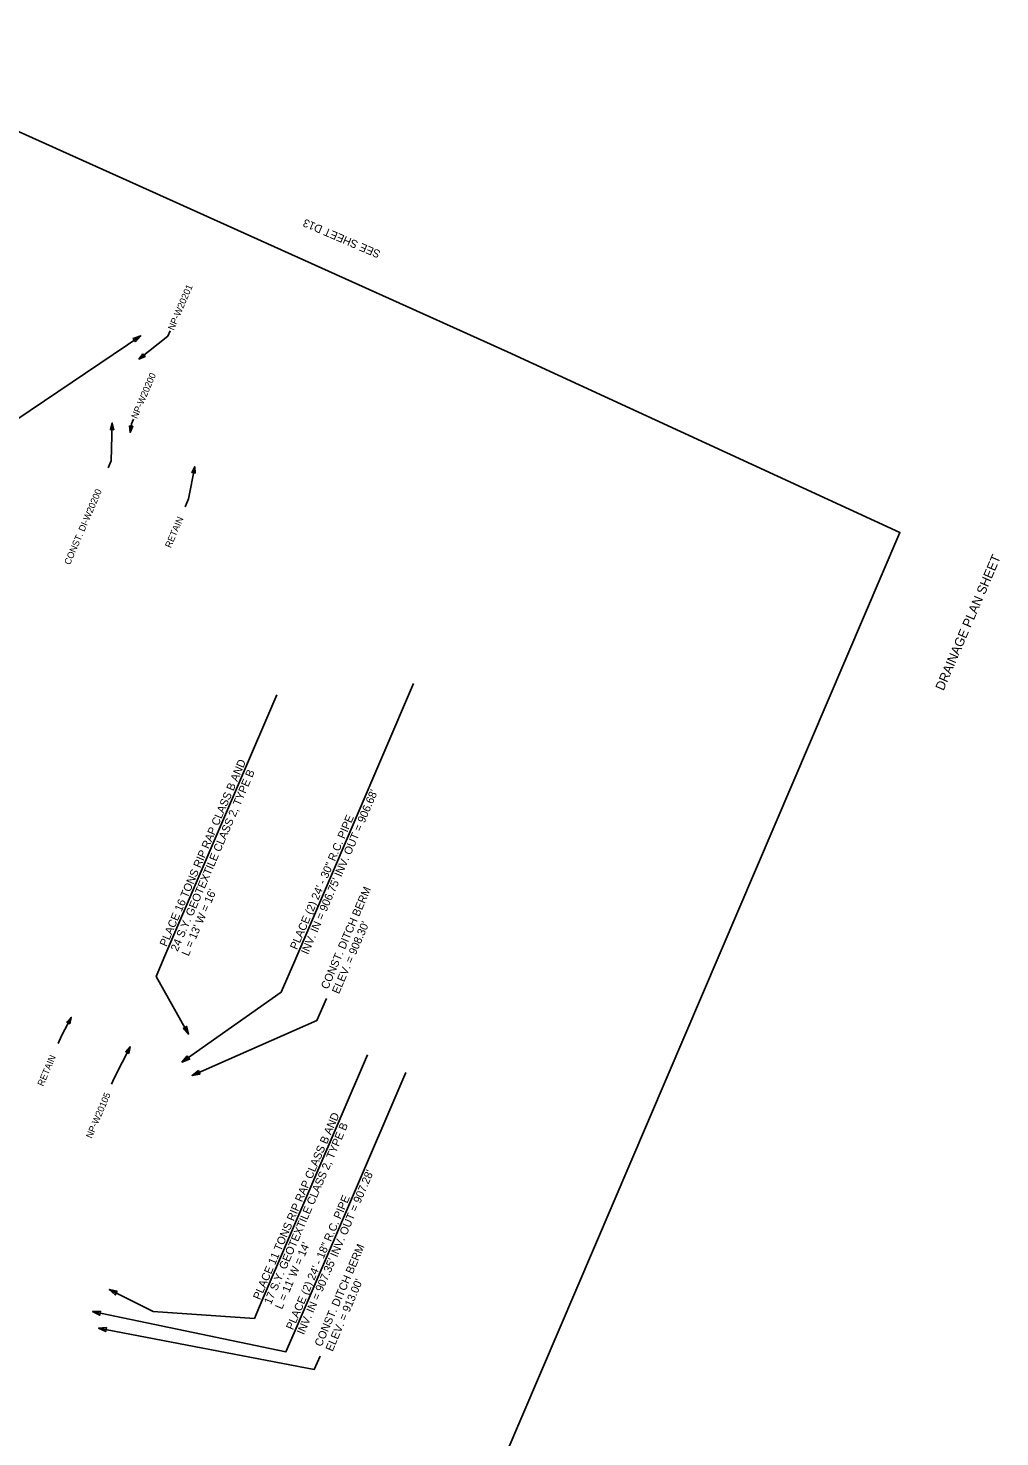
# Model space of a CAD drawing. Extents: x 1615213 to 1616738, y 1098243 to 1100099.
# Drawn here: x 1616009 to 1616738, y 1098952 to 1100008 of the extents above; entities that cross this region are included whole.
import ezdxf

# ---------------------------------------------------------------- set-up
doc = ezdxf.new("R2010")
doc.units = 0
for name, color, linetype in [('Plan_Clip', 7, 'Continuous'), ('RD_SHT_MatchLine', 7, 'Continuous'), ('RD_TX_Drainage', 7, 'Continuous'), ('RD_TX_RoadID', 7, 'Continuous')]:
    doc.layers.add(name, color=color, linetype=linetype)

msp = doc.modelspace()

# ---------------------------------------------------------------- linework, layer by layer
at = {"layer": 'Plan_Clip'}
msp.add_lwpolyline([(1615502.7, 1098507.9), (1615778.5, 1098389.7), (1616070.1, 1098243.5), (1616662.9, 1099630.3), (1616368.7, 1099765.8), (1616095.1, 1099888.9), (1615829.5, 1100008.4), (1615766.4, 1099858.4), (1615733.7, 1099872.1), (1615213.1, 1098634.6)], close=True, dxfattribs=at)
msp.add_lwpolyline([(1615502.7, 1098507.9), (1615778.5, 1098389.7), (1616070.1, 1098243.5), (1616662.9, 1099630.3), (1616368.7, 1099765.8), (1616095.1, 1099888.9), (1615829.5, 1100008.4), (1615766.4, 1099858.4), (1615733.7, 1099872.1), (1615213.1, 1098634.6)], close=True, dxfattribs=at)
msp.add_lwpolyline([(1615502.7, 1098507.9), (1615778.5, 1098389.7), (1616070.1, 1098243.5), (1616662.9, 1099630.3), (1616368.7, 1099765.8), (1616095.1, 1099888.9), (1615829.5, 1100008.4), (1615766.4, 1099858.4), (1615733.7, 1099872.1), (1615213.1, 1098634.6)], close=True, dxfattribs=at)
msp.add_lwpolyline([(1615502.7, 1098507.9), (1615778.5, 1098389.7), (1616070.1, 1098243.5), (1616662.9, 1099630.3), (1616368.7, 1099765.8), (1616095.1, 1099888.9), (1615829.5, 1100008.4), (1615766.4, 1099858.4), (1615733.7, 1099872.1), (1615213.1, 1098634.6)], close=True, dxfattribs=at)
msp.add_lwpolyline([(1615502.7, 1098507.9), (1615778.5, 1098389.7), (1616070.1, 1098243.5), (1616662.9, 1099630.3), (1616368.7, 1099765.8), (1616095.1, 1099888.9), (1615829.5, 1100008.4), (1615766.4, 1099858.4), (1615733.7, 1099872.1), (1615213.1, 1098634.6)], close=True, dxfattribs=at)
msp.add_lwpolyline([(1615502.7, 1098507.9), (1615778.5, 1098389.7), (1616070.1, 1098243.5), (1616662.9, 1099630.3), (1616368.7, 1099765.8), (1616095.1, 1099888.9), (1615829.5, 1100008.4), (1615766.4, 1099858.4), (1615733.7, 1099872.1), (1615213.1, 1098634.6)], close=True, dxfattribs=at)
at = {"layer": 'RD_TX_Drainage'}
for p, q in [((1616298.2, 1099516.9), (1616209, 1099308.9)), ((1616195.7, 1099508.5), (1616111.7, 1099312.7)), ((1616263.7, 1099238.6), (1616183.9, 1099052.8)), ((1616292.3, 1099225.3), (1616208.6, 1099030.1))]:
    msp.add_line(p, q, dxfattribs=at)
for points in [[(1615890.6, 1099613.1), (1615907.4, 1099652.1), (1616093.6, 1099777.7)], [(1616115.7, 1099781.4), (1616114, 1099777.5), (1616092.2, 1099760.2)], [(1616088.1, 1099715.2), (1616086.6, 1099711.8), (1616085.6, 1099705.3)], [(1616069.2, 1099678.8), (1616071.5, 1099684), (1616072.2, 1099712.2)], [(1616126.8, 1099649.5), (1616129.3, 1099655.4), (1616134.1, 1099679.5)], [(1616111.7, 1099312.7), (1616105.1, 1099297.3), (1616129.4, 1099254)], [(1616209, 1099308.9), (1616198.9, 1099285.5), (1616124.5, 1099233.1)], [(1616232.8, 1099280.7), (1616225.7, 1099264.2), (1616132.1, 1099223.1)], [(1616031.7, 1099247.1), (1616034.1, 1099252.8), (1616041.5, 1099266.6)], [(1616071.7, 1099216.5), (1616073.6, 1099220.9), (1616085.6, 1099244.5)], [(1616183.9, 1099052.8), (1616178.8, 1099040.8), (1616103, 1099046.1), (1616069.9, 1099062.5)], [(1616208.6, 1099030.1), (1616202.5, 1099015.8), (1616057.5, 1099045.9)], [(1616228, 1099012.6), (1616223.7, 1099002.6), (1616061.9, 1099033.6)]]:
    msp.add_lwpolyline(points, dxfattribs=at)
for points in [[(1616089.7, 1099773.1), (1616093.6, 1099777.7), (1616088, 1099775.7)], [(1616095.2, 1099764.2), (1616092.2, 1099760.2), (1616096.8, 1099762.2)], [(1616073.4, 1099707.3), (1616072.2, 1099712.2), (1616070.8, 1099707.4)], [(1616085.1, 1099710.3), (1616085.6, 1099705.3), (1616087.6, 1099709.9)], [(1616134.5, 1099674.6), (1616134.1, 1099679.5), (1616131.9, 1099675.1)], [(1616040.4, 1099261.8), (1616041.5, 1099266.6), (1616038.1, 1099263)], [(1616125.3, 1099258.3), (1616129.4, 1099254), (1616128, 1099259.8)], [(1616084.6, 1099239.6), (1616085.6, 1099244.5), (1616082.3, 1099240.8)], [(1616128.4, 1099237.7), (1616124.5, 1099233.1), (1616130.2, 1099235.2)], [(1616136.8, 1099226.8), (1616132.1, 1099223.1), (1616138, 1099224)], [(1616075.8, 1099061.3), (1616069.9, 1099062.5), (1616074.4, 1099058.5)], [(1616063.5, 1099046.3), (1616057.5, 1099045.9), (1616062.8, 1099043.2)], [(1616067.9, 1099034.1), (1616061.9, 1099033.6), (1616067.3, 1099031)]]:
    msp.add_lwpolyline(points, close=True, dxfattribs=at)

# ---------------------------------------------------------------- texts
at = {"layer": 'RD_SHT_MatchLine'}
msp.add_text('SEE SHEET D13', height=6, rotation=156.8359, dxfattribs=at).set_placement((1616273.9, 1099841.2))
at = {"layer": 'RD_TX_Drainage'}
for s, height, p in [('NP-W20201', 5, (1616118.3, 1099781.4)), ('NP-W20200', 5, (1616090.8, 1099715.1)), ('CONST. DI-W20200', 5, (1616040.5, 1099605.5)), ('RETAIN', 5, (1616116.1, 1099618.2)), ('PLACE 16 TONS RIP RAP CLASS B AND', 6, (1616112.9, 1099319.2)), ('24 S.Y. GEOTEXTILE CLASS 2, TYPE B', 6, (1616121.2, 1099315.6)), ("INV. IN = 906.75' INV. OUT = 906.68'", 6, (1616219, 1099313.3)), ('PLACE (2) 24\' - 30" R.C. PIPE', 6, (1616210.7, 1099316.9)), ("L = 13' W = 16'", 6, (1616129.4, 1099312.1)), ('CONST. DITCH BERM', 6, (1616233.9, 1099287.2)), ("ELEV. = 908.30'", 6, (1616242.2, 1099283.7)), ('RETAIN', 5, (1616020.4, 1099214.5)), ('NP-W20105', 5, (1616056.8, 1099175.4)), ('PLACE 11 TONS RIP RAP CLASS B AND', 6, (1616183, 1099054.3)), ('17 S.Y. GEOTEXTILE CLASS 2, TYPE B', 6, (1616191.2, 1099050.8)), ("INV. IN = 907.35' INV. OUT = 907.28'", 6, (1616215.9, 1099028.1)), ('PLACE (2) 24\' - 18" R.C. PIPE', 6, (1616207.7, 1099031.7)), ("L = 11' W = 14'", 6, (1616199.5, 1099047.2)), ('CONST. DITCH BERM', 6, (1616229.1, 1099019.2)), ("ELEV. = 913.00'", 6, (1616237.4, 1099015.6))]:
    msp.add_text(s, height=height, rotation=66.7846, dxfattribs=at).set_placement(p)
at = {"layer": 'RD_TX_RoadID'}
msp.add_text('DRAINAGE PLAN SHEET', height=6.983, rotation=66.7846, dxfattribs=at).set_placement((1616695.6, 1099511.1))

doc.saveas('drawing.dxf')
